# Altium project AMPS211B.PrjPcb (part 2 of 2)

## Sheet AMPS211B_PwrMod_Regs.SchDoc: AMPS211B_PwrMod_Regs
size 431 x 279 mm; Date: Not shown in title block; ApprovedBy: Not shown in title block; CheckedBy: Not shown in title block; Author: Not shown in title block; CompanyName: Not shown in title block; Engineer: Not shown in title block; Organization: Not shown in title block; Address1: Not shown in title block; Address2: Not shown in title block; Address3: Not shown in title block; Address4: Not shown in title block; DocumentNumber: 2; Revision: Use project parameter SCH_Rev; SheetNumber: 2; SheetTotal: 4; PageSetup: Record=PageOptions¦CenterHorizontal=True¦CenterVertical=True¦PrintScale=1.00¦XCorrection=1.00¦YCorrection=1.00¦PrintKind=0¦BorderSize=5000000¦LeftOffset=0¦BottomOffset=0¦Orientation=2¦PaperLength=1000¦PaperWidth=1000¦Scale=100¦PaperSource=15¦PrintQuality=600¦MediaType=1¦DitherType=10¦PaperKind=Letter¦PrintScaleMode=1
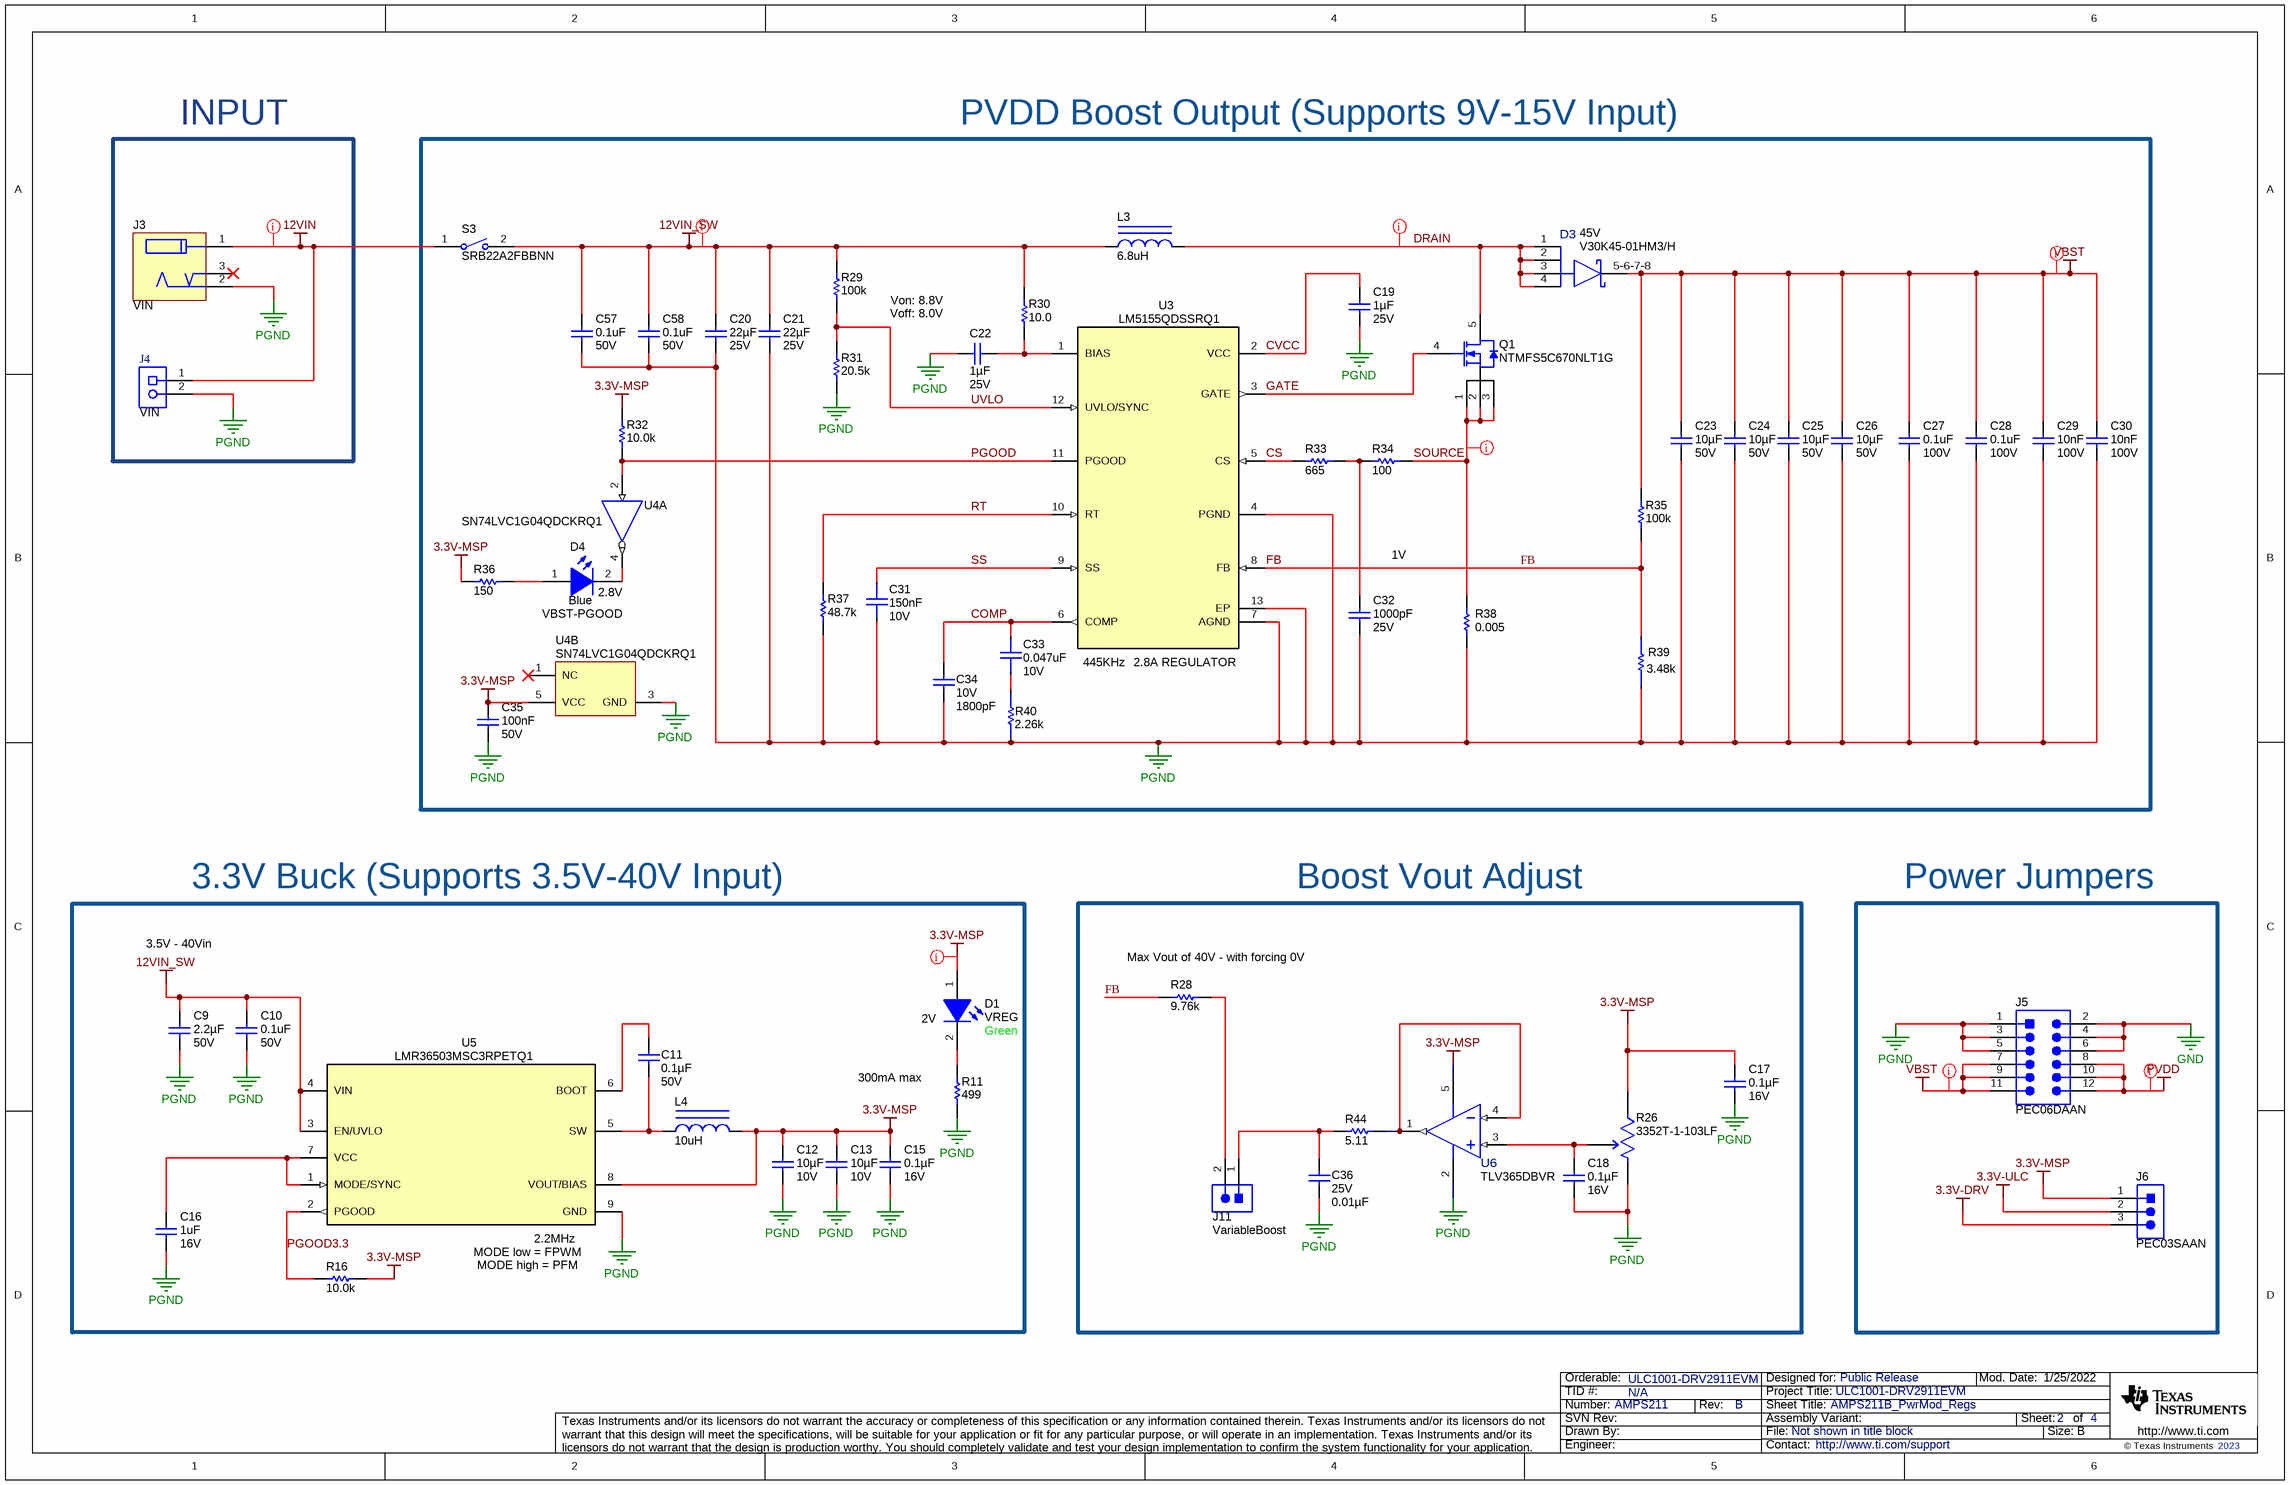
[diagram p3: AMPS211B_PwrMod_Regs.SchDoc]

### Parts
C9  Cap_F: 2.2µF  VDC_V: 50V  [0805L]  (hidden comment: CGA4J3X7R1H225K125AB)
C10  VDC_V: 50V  ValueDisplayed: 0.1uF  [0603L]  (hidden comment: CGA3E2X7R1H104K080AA)
C11  ValueDisplayed: 0.1µF  VDC_V: 50V  [0402L]  (hidden comment: CGA2B3X7R1H104K050BD)
C12  Cap_F: 10µF  VDC_V: 10V  [0805L]  (hidden comment: GCJ21BR71A106KE01L)
C13  Cap_F: 10µF  VDC_V: 10V  [0805L]  (hidden comment: GCJ21BR71A106KE01L)
C15  VDC_V: 16V  ValueDisplayed: 0.1µF  [0402L]  (hidden comment: GCM155R71C104JA55D)
C16  VDC_V: 16V  ValueDisplayed: 1uF  [0402L]  (hidden comment: EMK105BJ105KVHF)
C17  VDC_V: 16V  ValueDisplayed: 0.1µF  [0402L]  (hidden comment: GCM155R71C104JA55D)
C18  VDC_V: 16V  ValueDisplayed: 0.1µF  [0402L]  (hidden comment: GCM155R71C104JA55D)
C19  Cap_F: 1µF  VDC_V: 25V  [0603S]  (hidden comment: GCM188R71E105KA64D)
C20  VDC_V: 25V  ValueDisplayed: 22µF  [1210_270L]  (hidden comment: CL32B226KAJNFNE)
C21  VDC_V: 25V  ValueDisplayed: 22µF  [1210_270L]  (hidden comment: CL32B226KAJNFNE)
C22  Cap_F: 1µF  VDC_V: 25V  [0603S]  (hidden comment: GCM188R71E105KA64D)
C23  VDC_V: 50V  ValueDisplayed: 10µF  [1210_270L]  (hidden comment: CL32B106KBJNNWE)
C24  VDC_V: 50V  ValueDisplayed: 10µF  [1210_270L]  (hidden comment: CL32B106KBJNNWE)
C25  VDC_V: 50V  ValueDisplayed: 10µF  [1210_270L]  (hidden comment: CL32B106KBJNNWE)
C26  VDC_V: 50V  ValueDisplayed: 10µF  [1210_270L]  (hidden comment: CL32B106KBJNNWE)
C27  VDC_V: 100V  ValueDisplayed: 0.1uF  [0603S]  (hidden comment: GRM188R72A104KA35J)
C28  VDC_V: 100V  ValueDisplayed: 0.1uF  [0603S]  (hidden comment: GRM188R72A104KA35J)
C29  Cap_F: 10nF  VDC_V: 100V  [0603S]  (hidden comment: CGA3E2X7R2A103K080AA)
C30  Cap_F: 10nF  VDC_V: 100V  [0603S]  (hidden comment: CGA3E2X7R2A103K080AA)
C31  ValueDisplayed: 150nF  VDC_V: 10V  [FP-CGA2B1X7R1A154M050BC_0402-MFG]  (hidden comment: CGA2B1X7R1A154M050BC)
C32  VDC_V: 25V  ValueDisplayed: 1000pF  [0201_033L]  (hidden comment: CGA1A2X7R1E102K030BA)
C33  ValueDisplayed: 0.047uF  VDC_V: 10V  [FP-LMF105B7473KVHF_0402-MFG]  (hidden comment: LMF105B7473KVHF)
C34  VDC_V: 10V  ValueDisplayed: 1800pF  [0201L]  (hidden comment: GRM033R71A182KA01D)
C35  Cap_F: 100nF  VDC_V: 50V  [0603L]  (hidden comment: CGA3E2X7R1H104K080AA)
C36  VDC_V: 25V  ValueDisplayed: 0.01µF  [0402]  (hidden comment: CL05B103KA5NNNC)
C57  VDC_V: 50V  ValueDisplayed: 0.1uF  [0603L]  (hidden comment: CGA3E2X7R1H104K080AA)
C58  VDC_V: 50V  ValueDisplayed: 0.1uF  [0603L]  (hidden comment: CGA3E2X7R1H104K080AA)
D1  VREG  value Green  Value2: 2V  [LTST-C193_Green]
D3  V30K45-01HM3/H  Vf_V: 45V  [FP-V30K45-01HM3-H_FlatPAK5x6-MFG]
D4  VBST-PGOOD  value Blue  Value2: 2.8V  [LTST-C193_Blue]
J3  VIN  [CONN_RAPC712X]
J4  VIN  [Molex_039544-3002]
J5  PEC06DAAN  [CONN_PEC06DAAN]
J6  PEC03SAAN  [CONN_PEC03SAAN]
J11  VariableBoost  [Samtec_TSW-102-07-T-S]
L3  ValueDisplayed: 6.8uH  [XAL1010]  (hidden comment: XAL1010-682MEB)
L4  ValueDisplayed: 10uH  [XPL2010]  (hidden comment: XPL2010-103MLB)
Q1  NTMFS5C670NLT1G  [SO-8FL]
R11  ValueDisplayed: 499  [0603L]  (hidden comment: CRCW0603499RFKEAC)
R16  ValueDisplayed: 10.0k  [0402S]  (hidden comment: RC0402FR-0710KL)
R26  3352T-1-103LF  [Bourns_3352T]
R28  ValueDisplayed: 9.76k  [0402]  (hidden comment: CRCW04029K76FKED)
R29  ValueDisplayed: 100k  [0402L]  (hidden comment: ERJ-2RKF1003X)
R30  ValueDisplayed: 10.0  [0603S]  (hidden comment: CRCW060310R0FKEA)
R31  ValueDisplayed: 20.5k  [0402S]  (hidden comment: CRCW040220K5FKED)
R32  ValueDisplayed: 10.0k  [0402S]  (hidden comment: RC0402FR-0710KL)
R33  ValueDisplayed: 665  [0402S]  (hidden comment: ERJ-2RKF1000X)
R34  ValueDisplayed: 100  [0402S]  (hidden comment: ERJ-2RKF1000X)
R35  ValueDisplayed: 100k  [0603L]  (hidden comment: CRCW0603100KFKEA)
R36  ValueDisplayed: 150  [0402S]  (hidden comment: CRCW0402150RFKED)
R37  ValueDisplayed: 48.7k  [0402L]  (hidden comment: CRCW040248K7FKED)
R38  ValueDisplayed: 0.005  [CRE2512-R5_R9]  (hidden comment: CRE2512-FZ-R005E-3)
R39  value 3.48k  [FP-RK73H1JTTD3481F_0603-MFG]  (hidden comment: RK73H1JTTD3481F)
R40  Res_ohm: 2.26k  [FP-ERJ-1GNF2261C_0201-MFG]  (hidden comment: ERJ-1GNF2261C)
R44  ValueDisplayed: 5.11  [0402]  (hidden comment: CRCW04025R11FKED)
S3  SRB22A2FBBNN  [SW_SRB22A2FBBNN]
U3  LM5155QDSSRQ1  [DSS0012C]
U4  SN74LVC1G04QDCKRQ1  [DCK0005A_L]  (parts A,B of 2)
U5  LMR36503MSC3RPETQ1  [RPE0009A]
U6  TLV365DBVR  [DBV0005A-MFG]

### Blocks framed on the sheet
Max Vout of 40V - with forcing 0V: C17 C18 C36 J11 R26 R28 R44 U6

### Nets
3.3V-DRV: J6.3
3.3V-MSP: C12.1 C13.1 C15.1 C17.1 C35.1 D1.1(A) J6.1 L4.2 R16.2 R26.1(CCW) R32.1 R36.1 U4.5(VCC) U5.8(VOUT/BIAS) U6.5(V+)
3.3V-ULC: J6.2
12VIN: J3.1 J4.1 S3.1
12VIN_SW: C9.1 C10.1 C20.1 C21.1 C57.1 C58.1 L3.1 R29.2 R30.2 S3.2 U5.3(EN/UVLO) U5.4(VIN)
GND: J5.2 J5.4 J5.6
PGND: C9.2 C10.2 C12.2 C13.2 C15.2 C16.2 C17.2 C18.2 C19.2 C20.2 C21.2 C22.2 C23.2 C24.2 C25.2 C26.2 C27.2 C28.2 C29.2 C30.2 C31.2 C32.2 C34.2 C35.2 C36.2 C57.2 C58.2 J3.2 J4.2 J5.1 J5.3 J5.5 R11.1 R26.3(CW) R31.1 R37.1 R38.1 R39.1 R40.1 U3.4(PGND) U3.7(AGND) U3.13(EP) U4.3(GND) U5.9(GND) U6.2(V-)
PVDD: J5.8 J5.10 J5.12
VBST: C23.1 C24.1 C25.1 C26.1 C27.1 C28.1 C29.1 C30.1 D3.5-6-7-8(CATHODE) J5.7 J5.9 J5.11 R35.2
COMP: C33.2 C34.1 U3.6(COMP)
CS: R33.1 U3.5(CS)
CVCC: C19.1 U3.2(VCC)
DRAIN: D3.1(ANODE) D3.2(ANODE) D3.3(ANODE) D3.4(ANODE) L3.2 Q1.5(D)
FB: R28.1 R35.1 R39.2 U3.8(FB)
GATE: Q1.4(G) U3.3(GATE)
PGOOD: R32.2 U3.11(PGOOD) U4.2(A)
PGOOD3.3: R16.1 U5.2(PGOOD)
RT: R37.2 U3.10(RT)
SOURCE: Q1.1(S) Q1.2(S) Q1.3(S) R34.2 R38.2
SS: C31.1 U3.9(SS)
UVLO: R29.1 R31.2 U3.12(UVLO/SYNC)
NetC11_1: C11.1 U5.6(BOOT)
NetC11_2: C11.2 L4.1 U5.5(SW)
NetC16_1: C16.1 U5.1(MODE/SYNC) U5.7(VCC)
NetC18_1: C18.1 R26.2(WIPER) U6.3(+IN)
NetC22_1: C22.1 R30.1 U3.1(BIAS)
NetC32_1: C32.1 R33.2 R34.1
NetC33_1: C33.1 R40.2
NetC36_1: C36.1 J11.1 R44.1
NetD1_2: D1.2(K) R11.2
NetD4_1: D4.1(A) R36.2
NetD4_2: D4.2(K) U4.4(Y)
NetJ11_2: J11.2 R28.2
NetR44_2: R44.2 U6.1(VOUT) U6.4(-IN)

Not connected (* = marked no-connect by the designer): J3 3*; U4 1(NC)*

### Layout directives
net class Power: 3.3V-MSP, 12VIN, 12VIN_SW, DRAIN, PVDD, SOURCE, VBST

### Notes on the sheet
- INPUT
- PVDD Boost Output (Supports 9V-15V Input)
- Von: 8.8V
- Voff: 8.0V
- 1V
- (near U3) 445KHz
- (near U3) 2.8A REGULATOR
- 3.3V Buck (Supports 3.5V-40V Input)
- Boost Vout Adjust
- Power Jumpers
- 3.5V - 40Vin
- 300mA max
- (near U5) 2.2MHz
- (near U5) MODE low = FPWM
- (near U5) MODE high = PFM

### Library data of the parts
C9 = CMP-0007977-2: CAP, CERM, 2.2 uF, 50 V, +/- 10%, X7R, AEC-Q200 Grade 1, 0805; Manufacturer: TDK; TaMin_C: -55°C; ESR_ohm: 3.288m; Polarized: N; SizeAreaWB_mm2: 6.75; Value1: 0.003288 ohm; U/M: EA; Value: 2.2uF; TaMax_C: 125°C; SizeZ_mm: 1.45; SizeX_mm: 2; SizeY_mm: 1.25; Cap_Case: 0805; SizeArea_mm2: 2.5; AEC Qualified: Y; IRMS_A: 3.6003A; AEC Grade: 1; AEC Category: Q200
C10 C57 C58 = CMP-0007078-4: CAP, CERM, 0.1 uF, 50 V, +/- 10%, X7R, AEC-Q200 Grade 1, 0603; Manufacturer: TDK; TaMin_C: -55°C; ESR_ohm: 0.0296; Polarized: N; SizeAreaWB_mm2: 4.68; Value1: 0.0296 ohm; U/M: EA; Value: 0.1uF; TaMax_C: 125°C; SizeZ_mm: 1; SizeX_mm: 1.6; SizeY_mm: 0.8; Cap_Case: 0603; SizeArea_mm2: 1.28; AEC Qualified: Y; Cap_F: 100nF; IRMS_A: 971.99mA; AEC Category: Q200
C11 = CMP-0084548-1: CAP, CERM, 0.1 µF, 50 V,+/- 10%, X7R, AEC-Q200 Grade 1, 0402; Manufacturer: TDK; SizeZ_mm: 0.6; TaMax_C: 125°C; Cap_F: 100nF; Polarized: N; SizeX_mm: 1; Value: 0.1uF; AEC Category: Q200; TaMin_C: -55°C; SizeArea_mm2: 0.5; SizeAreaWB_mm2: 3; Cap_Case: 0402; U/M: EA; AEC Qualified: Y
C12 C13 = CMP-0079153-1: CAP, CERM, 10 µF, 10 V,+/- 10%, X7R, AEC-Q200 Grade 1, 0805; Manufacturer: MuRata; SizeAreaWB_mm2: 6.75; SizeArea_mm2: 2.5; AEC Qualified: Y; AEC Category: Q200; Value: 10uF; TaMax_C: 125°C; SizeZ_mm: 1.45; AEC Grade: 1; Polarized: N; TaMin_C: -55°C; SizeY_mm: 1.25; U/M: EA; SizeX_mm: 2; Cap_Case: 0805
C15 C17 C18 = CMP-0080702-1: CAP, CERM, 0.1 µF, 16 V,+/- 5%, X7R, AEC-Q200 Grade 1, 0402; Manufacturer: MuRata; Cap_F: 100nF; SizeAreaWB_mm2: 3; SizeArea_mm2: 0.5; AEC Qualified: Y; AEC Category: Q200; Value: 0.1uF; TaMax_C: 125°C; SizeZ_mm: 0.6; AEC Grade: 1; Polarized: N; TaMin_C: -55°C; U/M: EA; Cap_Case: 0402
C16 = CMP-0006347-2: CAP, CERM, 1 uF, 16 V, +/- 10%, X5R, 0402; Manufacturer: Taiyo Yuden; TaMin_C: -55°C; Polarized: N; SizeAreaWB_mm2: 3; Value1: Unknown; U/M: EA; Value: 1uF; TaMax_C: 85°C; SizeZ_mm: 0.6; SizeX_mm: 1; SizeY_mm: 0.5; Cap_Case: 0402; Cap_F: 1µF; AEC Category: Q200
C19 C22 = CMP-0007139-4: CAP, CERM, 1 uF, 25 V, +/- 10%, X7R, AEC-Q200 Grade 1, 0603; Manufacturer: MuRata; TaMin_C: -55°C; Polarized: N; SizeAreaWB_mm2: 4.68; Value1: Unknown; U/M: EA; Value: 1uF; TaMax_C: 125°C; SizeZ_mm: 1; SizeX_mm: 1.6; SizeY_mm: 0.8; Cap_Case: 0603; SizeArea_mm2: 1.28; AEC Qualified: Y; AEC Category: Q200
C20 C21 = CMP-0080066-1: CAP, CERM, 22 µF, 25 V,+/- 10%, X7R, 1210; Manufacturer: Samsung Electro-Mechanics; TaMin_C: -55°C; Polarized: N; SizeAreaWB_mm2: 14.7; U/M: EA; Value: 22uF; TaMax_C: 125°C; SizeZ_mm: 2.7; SizeX_mm: 3.2; SizeY_mm: 2.5; Cap_Case: 1210; SizeArea_mm2: 8; AEC Category: Q200
C23-C26 = CMP-0079201-1: CAP, CERM, 10 µF, 50 V,+/- 10%, X7R, 1210; Manufacturer: Samsung Electro-Mechanics; TaMin_C: -55°C; ESR_ohm: 5m; Polarized: N; SizeAreaWB_mm2: 14.7; Value1: 0.005 ohm; U/M: EA; Value: 10uF; TaMax_C: 125°C; SizeZ_mm: 2.7; SizeX_mm: 3.2; SizeY_mm: 2.5; Cap_Case: 1210; SizeArea_mm2: 8; AEC Category: Q200
C27 C28 = CMP-0007470-5: CAP, CERM, 0.1 uF, 100 V, +/- 10%, X7R, 0603; Manufacturer: MuRata; TaMin_C: -55°C; Polarized: N; SizeAreaWB_mm2: 4.68; Value1: Unknown; U/M: EA; Value: 0.1uF; TaMax_C: 125°C; SizeZ_mm: 1; SizeX_mm: 1.6; SizeY_mm: 0.8; Cap_Case: 0603; SizeArea_mm2: 1.28; CompType: Capacitor; Cap_F: 100nF; AEC Category: Q200
C29 C30 = CMP-0007082-4: CAP, CERM, 0.01 uF, 100 V, +/- 10%, X7R, AEC-Q200 Grade 1, 0603; Manufacturer: TDK; TaMin_C: -55°C; ESR_ohm: 2.35428d; Polarized: N; SizeAreaWB_mm2: 4.68; Value1: 0.235428 ohm; U/M: EA; Value: 0.01uF; TaMax_C: 125°C; SizeZ_mm: 1; SizeX_mm: 1.6; SizeY_mm: 0.8; Cap_Case: 0603; SizeArea_mm2: 1.28; CompType: Capacitor; AEC Qualified: Y; IRMS_A: 3.96995dA; AEC Category: Q200
C31 = CMP-0088625-1: 0.15µF ±20% 10V Ceramic Capacitor X7R 0402 (1005 Metric); Manufacturer: TDK; AEC Grade: Grade 1; AEC Qualified: Yes; TempCo: 15%; SizeZ_mm: 0.55mm
C32 = CMP-0009645-3: CAP, CERM, 1000 pF, 25 V, +/- 10%, X7R, AEC-Q200 Grade 1, 0201; Manufacturer: TDK; TaMin_C: -55°C; ESR_ohm: 2.5722; Polarized: N; SizeAreaWB_mm2: 2.08; Value1: 2.5722 ohm; U/M: EA; Value: 1000pF; TaMax_C: 125°C; SizeZ_mm: 0.33; SizeX_mm: 0.6; SizeY_mm: 0.3; Cap_Case: 0201_033; SizeArea_mm2: 0.18; AEC Qualified: Y; Cap_F: 1nF; IRMS_A: 143.158mA; AEC Grade: 1; AEC Category: Q200
C33 = CMP-0088629-1: Multilayer Ceramic Capacitor 0.047uF 10V 10% 0402 Paper T/R; Manufacturer: Taiyo Yuden; Cap_F: 47nF; AEC Qualified: Yes; Temperature Characteristic: X7R; TempCo: 15%; AEC Grade: Grade 1; SizeZ_mm: 0.55mm
C34 = CMP-0009735-1: CAP, CERM, 1800 pF, 10 V, +/- 10%, X7R, 0201; Manufacturer: MuRata; TaMin_C: -55°C; Polarized: N; SizeAreaWB_mm2: 2.08; Value1: Unknown; U/M: EA; Value: 1800pF; TaMax_C: 125°C; SizeZ_mm: 0.26; SizeX_mm: 0.6; SizeY_mm: 0.3; Cap_Case: 0201; SizeArea_mm2: 0.18; Cap_F: 1.8nF; AEC Category: Q200
C35 = CMP-0007078-4: CAP, CERM, 0.1 uF, 50 V, +/- 10%, X7R, AEC-Q200 Grade 1, 0603; Manufacturer: TDK; TaMin_C: -55°C; ESR_ohm: 0.0296; Polarized: N; SizeAreaWB_mm2: 4.68; Value1: 0.0296 ohm; U/M: EA; Value: 0.1uF; TaMax_C: 125°C; SizeZ_mm: 1; SizeX_mm: 1.6; SizeY_mm: 0.8; Cap_Case: 0603; SizeArea_mm2: 1.28; AEC Qualified: Y; IRMS_A: 971.99mA; AEC Category: Q200
C36 = CMP-0860561-1: CAP, CERM, 0.01 µF, 25 V,+/- 10%, X7R, 0402; Manufacturer: Samsung Electro-Mechanics; U/M: EA; SizeArea_mm2: 0.5; Value: 0.01uF; TaMin_C: -55°C; SizeZ_mm: 0.6; Polarized: N; SizeX_mm: 1; TaMax_C: 125°C; SizeAreaWB_mm2: 3; Cap_F: 10nF; AEC Category: Q200
D1 = CMP-0079921-3: LED, Green, SMD; PartNumber: LTST-C193KGKT-5A; Manufacturer: Lite-On; Tjmax_C: 85°C; SizeY_mm: 0.8; Io_A: 5mA; SizeAreaWB_mm2: 4.68; Type: AlInGaP; SizeX_mm: 1.6; SizeZ_mm: 0.45; SizeArea_mm2: 1.28; Value1: W
D3 = CMP-0088390-3: Diode Schottky 45V 30A Surface Mount FlatPAK (5x6); Manufacturer: Vishay; ValueDisplayed: 4000pF; AEC Category: Q101; SizeZ_mm: 1.09mm; AEC Grade: Grade 0; AEC Qualified: Yes; TJmax_C: 150°C; Forward Current: 5A; Peak Reverse Current: 2mA; Max Surge Forward Current: 240A
D4 = CMP-0002938-3: LED, Blue, SMD; PartNumber: LTST-C193TBKT-5A; Manufacturer: Lite-On; Angle: 130; Power_TotalModule: 76mW; Type: InGaN; Tjmax_C: 80°C; Value1: 0.076W; Io_A: 5mA; Ir_A: 10µA; LuminousIntensity_IV: 15
J3 = CMP-0074931-1: Power Jack, mini, 2.5mm OD, R/A, TH; Manufacturer: Switchcraft; PartNumber: RAPC712X; CNHeader: False; Green_Lifecycle: Not Set; Green_REACh: Incomplete
J4 = CMP-0055345-1: Terminal Block, 5.08mm, 2x1, TH; Manufacturer: Molex; PartNumber: 039544-3002; CNHeader: FALSE; Current_A: 15A; Gender: Female; Voltage_V: 300V; Row_Count: 1; Pitch_mm: 5.08; ContactFinish: Tin; CT: TRUE; Cert_UL: Y
J5 = CMP-0054551-2: Header, 100mil, 6x2, Tin, TH; Manufacturer: Sullins Connector Solutions; Current_A: 3A; Green_Lifecycle: Not Set; Shrouded: N; Gender: Male; Green_REACh: Incomplete; Voltage_V: 1.8kV; Row_Count: 2; RowSpacing_mm: 2.54; Cert_UL: Y
J6 = CMP-0002338-1: Header, 100mil, 3x1, Tin, TH; Manufacturer: Sullins Connector Solutions; CNHeader: TRUE; Current_A: 3A; Green_Lifecycle: Not Set; Shrouded: N; Gender: Male; Green_REACh: Incomplete; Voltage_V: 1.8kV; Row_Count: 1; Pitch_mm: 2.54; CT: FALSE; Cert_UL: Y
J11 = CMP-0075508-2: Header, 2.54 mm, 2x1, Tin, TH; PartNumber: TSW-102-07-T-S; Manufacturer: Samtec; Pitch_mm: 2.54; Cert_VDE: N; Gender: Male; Cert_CSA: Y; Voltage_V: 550V; Green_REACh: Passed; Current_A: 6.3A; Green_Lifecycle: Active; Row_Count: 1
L3 = CMP-0060953-1: Inductor, Shielded, Composite, 6.8 uH, 18.5 A, 0.01 ohm, SMD; Manufacturer: Coilcraft; Isat: 21.8A @ 30% inductance drop; Irms: 18.5A @ 40C rise; Green_Lifecycle: Not Set; SizeAreaWB_mm2: 159.6; DCR_ohm: 10m; Green_REACh: Incomplete; Value: 6.8uH; Imax_A: 18.5A; SizeZ_mm: 10; SizeX_mm: 11.3; SizeArea_mm2: 113; Ind_H: 6.8µH; AEC Category: Q200
L4 = CMP-0061167-1: Inductor, Shielded, Composite, 10 uH, 0.61 A, 0.56 ohm, SMD; Manufacturer: Coilcraft; Isat: 0.61A @ 30% inductance drop; Irms: 0.66A @ 40C rise; Green_Lifecycle: Not Set; SizeAreaWB_mm2: 8.7; DCR_ohm: 0.56; Green_REACh: Incomplete; Value: 10uH; Imax_A: 610mA; SizeZ_mm: 1; SizeX_mm: 2; SizeY_mm: 1.9; Value2: 0.61A; SizeArea_mm2: 3.8; Ind_H: 10µH; AEC Category: Q200
Q1 = CMP-0000853-1: MOSFET, N-CH, 60 V, 71 A, SO-8FL; Alternate Manufacturer: None; Manufacturer: ON Semiconductor; SizeZ_mm: 1.1; ChType: N; Value2: 20 nC; Value1: 0.008; VdsMax_V: 60V; SizeX_mm: 6.15; SizeY_mm: 5.15; Vgs_V: 20V; Value: 60V; Rdson45_ohm: 8.8m; SizeArea_mm2: 31.6725; AEC Category: Q101; IdsMax_A: 71A; SizeAreaWB_mm2: 58.2725; U/M: EA; QgTyp_nC: 20
R11 = CMP-0082532-1: RES, 499, 1%, 0.1 W, 0603; Manufacturer: Vishay-Dale; Value: 499; Value_Code: 499R; Power_W: 100mW; Value2: 0.1W; VDC_V: 75V; TempCo: 100 ppm/C; EIA_Code: E96; SizeAreaWB_mm2: 4.68; SizeX_mm: 1.6; SizeY_mm: 0.8; SizeZ_mm: 1; SizeArea_mm2: 1.28; AEC Qualified: N; AEC Category: Q200
R16 R32 = CMP-0078669-1: RES, 10.0 k, 1%, 0.063 W, 0402; Manufacturer: Yageo America; Power_W: 63mW; Green_Lifecycle: Active; TempCo: 100 ppm/C; Value_Code: 10k0; Green_REACh: Passed; Value: 10.0k; EIA_Code: E96; Res_ohm: 10k; SizeX_mm: 1; SizeY_mm: 0.5; SizeZ_mm: 0.6; Value2: 0.063W; CompType: Resistor; AEC Qualified: N; AEC Category: Q200
R26 = CMP-0093882-3: 10 kOhms 0.5W, 1/2W Through Hole Thumbwheel Potentiometer Top Adjustment; Manufacturer: Bourns; Value: 10kΩ; Voltage: 250V; TempCo: 100ppm/°C; Standoff Height: 0.64mm; Tolerance_%: 20%; Power: 500mW; AEC Qualified: No; SizeZ_mm: 4.32mm
R28 = CMP-0026622-3: RES, 9.76 k, 1%, 0.063 W, AEC-Q200 Grade 0, 0402; Manufacturer: Vishay-Dale; AEC Category: Q200; AEC Qualified: Y; AEC Grade: 0; Value2: 0.063W; Value_Code: 9k76; SizeY_mm: 0.5; SizeZ_mm: 0.6; VDC_V: 50V; SizeX_mm: 1; Value: 9.76k; Power_W: 63mW; EIA_Code: E96; TempCo: 100 ppm/C
R29 = CMP-0026659-2: RES, 100 k, 1%, 0.1 W, 0402; Manufacturer: Panasonic; Power_W: 100mW; TempCo: 100 ppm/C; U/M: EA; Value: 100k; EIA_Code: E96; SizeX_mm: 1; SizeY_mm: 0.5; SizeZ_mm: 0.6; Value2: 0.1W; AEC Qualified: Yes; VDC_V: 50V; AEC Category: Q200; AEC Grade: 0
R30 = CMP-0022003-4: RES, 10.0, 1%, 0.1 W, AEC-Q200 Grade 0, 0603; Manufacturer: Vishay-Dale; Power_W: 100mW; TempCo: 100 ppm/C; Value_Code: 10R0; Value: 10.0; EIA_Code: E96; Res_ohm: 10; SizeX_mm: 1.6; SizeY_mm: 0.8; SizeZ_mm: 1; Value2: 0.1W; SizeArea_mm2: 1.28; AEC Qualified: Y; VDC_V: 75V; AEC Category: Q200; AEC Grade: 0
R31 = CMP-0026163-2: RES, 20.5 k, 1%, 0.063 W, AEC-Q200 Grade 0, 0402; Manufacturer: Vishay-Dale; Power_W: 63mW; TempCo: 100 ppm/C; Value_Code: 20k5; Value: 20.5k; EIA_Code: E96; SizeX_mm: 1; SizeY_mm: 0.5; SizeZ_mm: 0.6; Value2: 0.063W; AEC Qualified: Y; VDC_V: 50V; AEC Category: Q200; AEC Grade: 0
R33 = CMP-0026501-2: RES, 665, 1%, 0.063 W, AEC-Q200 Grade 0, 0402; Manufacturer: Vishay-Dale; PartNumber: CRCW0402665RFKED; Power_W: 63mW; TempCo: 100 ppm/C; Value_Code: 665R; Value: 665; EIA_Code: E96; SizeX_mm: 1; SizeY_mm: 0.5; SizeZ_mm: 0.6; Value2: 0.063W; AEC Qualified: Y; VDC_V: 50V; AEC Category: Q200; AEC Grade: 0
R34 = CMP-0026656-1: RES, 100, 1%, 0.1 W, 0402; Manufacturer: Panasonic; Power_W: 100mW; TempCo: 100 ppm/C; Value_Code: 100R; U/M: EA; Value: 100; EIA_Code: E96; SizeX_mm: 1; SizeY_mm: 0.5; SizeZ_mm: 0.6; Value2: 0.1W; VDC_V: 50V; AEC Category: Q200
R35 = CMP-0021990-4: RES, 100 k, 1%, 0.1 W, AEC-Q200 Grade 0, 0603; Manufacturer: Vishay-Dale; Power_W: 100mW; TempCo: 100 ppm/C; Value: 100k; EIA_Code: E96; SizeX_mm: 1.6; SizeY_mm: 0.8; SizeZ_mm: 1; Value2: 0.1W; SizeArea_mm2: 1.28; AEC Qualified: Y; VDC_V: 75V; AEC Category: Q200; AEC Grade: 0
R36 = CMP-0026022-3: RES, 150, 1%, 0.063 W, AEC-Q200 Grade 0, 0402; Manufacturer: Vishay-Dale; Power_W: 63mW; TempCo: 100 ppm/C; Value_Code: 150R; Value: 150; EIA_Code: E96; SizeX_mm: 1; SizeY_mm: 0.5; SizeZ_mm: 0.6; Value2: 0.063W; AEC Qualified: Y; VDC_V: 50V; AEC Category: Q200; AEC Grade: 0
R37 = CMP-0026399-2: RES, 48.7 k, 1%, 0.063 W, AEC-Q200 Grade 0, 0402; Manufacturer: Vishay-Dale; Power_W: 63mW; TempCo: 100 ppm/C; Value_Code: 48k7; Value: 48.7k; EIA_Code: E96; SizeX_mm: 1; SizeY_mm: 0.5; SizeZ_mm: 0.6; Value2: 0.063W; AEC Qualified: Y; VDC_V: 50V; AEC Category: Q200; AEC Grade: 0
R38 = CMP-0015751-2: RES, 0.005, 1%, 3 W, AEC-Q200 Grade 0, 2512; Manufacturer: Bourns; Power_W: 3W; TempCo: 75 ppm/C; Value_Code: 5L000; U/M: EA; Value: 0.005; EIA_Code: E96; Res_ohm: 5m; SizeX_mm: 6.45; SizeY_mm: 3.35; SizeZ_mm: 0.9; SizeArea_mm2: 21.6075; AEC Qualified: Y; AEC Grade: 0; AEC Category: Q200
R39 = CMP-0098378-1: 3.48 kOhms ±1% 0.1W, 1/10W Chip Resistor 0603 (1608 Metric) Automotive AEC-Q200, Moisture Resistant Thick Film; Manufacturer: KOA Speer; Approved Alternate Part Number: 541-1.00HHCT-ND; AEC Grade: Grade 0; AEC Qualified: Yes; Power_W: 100mW; SizeZ_mm: 0.55mm; TempCo: 100ppm/°C; VDC_V: 75V; Standoff Height: 0mm
R40 = CMP-0088609-1: Res Thick Film 0201 2.26K Ohm 1% 1/20W ±200ppm/°C Molded SMD SMD T/R; Manufacturer: Panasonic Electronic Components; TempCo: 200%; VDC_V: 25V; SizeZ_mm: 0.26mm; AEC Grade: Grade 1; Power_W: 50mW; AEC Qualified: Yes
R44 = CMP-0026477-2: RES, 5.11, 1%, 0.063 W, AEC-Q200 Grade 0, 0402; Manufacturer: Vishay-Dale; Power_W: 63mW; TempCo: 100 ppm/C; Value_Code: 5R11; Value: 5.11; EIA_Code: E96; SizeX_mm: 1; SizeY_mm: 0.5; SizeZ_mm: 0.6; Value2: 0.063W; AEC Qualified: Y; VDC_V: 50V; AEC Category: Q200; AEC Grade: 0
S3 = CMP-0002275-1: Switch, SPST, Off-On, 10A, 125 V, TH; Manufacturer: Conergy; CurrentRating_mA: 10kA; PositionCount: 1; VDC_V: 125V
U3 = CMP-0081539-1: Automotive Grade 2.2-MHz Wide Input Non-synchronous Boost Controller, DSS0012C (WSON-12); Alternate PartNumber: LM5155QDSSTQ1; Alternate Manufacturer: Texas Instruments; SizeAreaWB_mm2: 12; SizeZ_mm: 0.8; SizeX_mm: 2; SizeY_mm: 3; SizeArea_mm2: 6; CompType: IC; AEC Qualified: Y; AEC Category: Q200
U4 = CMP-0051661-3: Automotive Catalog Single Inverter, DCK0005A, LARGE T&R; Manufacturer: Texas Instruments; Generic Part Number: SN74LVC1G04-Q1; Logic: Inverting; Input Type: CMOS/TTL; 3-State Output: No; Voltage(Nom)(V): 1.8,2.5,3.3,5; tpd @ Nom Voltage(Max)(ns): 7.5,5.2,4.2,3.7; Sub-Family: Inverting Buffer/Driver; Bits(#): 1; VCC(Min)(V): 1.65; F @ Nom Voltage(Max)(Mhz): 150; ICC @ Nom Voltage(Max)(mA): 0.01; Technology Family: LVC; Output Drive (IOL/IOH)(Max)(mA): 32/-32; Output Type: CMOS; VCC(Max)(V): 5.5; AEC Category: Q200; AEC Qualified: Y; CompType: IC; SizeAreaWB_mm2: 9.3; SizeArea_mm2: 4.2; SizeX_mm: 2.1; SizeY_mm: 2.0; SizeZ_mm: 1.1
U5 = CMP-0750083-1: LMR36503/06-Q1 Wide Input 60-V Synchronous, DC-DC Buck Converter, RPE0009A (VQFN-9); Alternate Manufacturer: Texas Instruments; Alternate PartNumber: LMR36503MSC3RPERQ1; AEC Category: Q200; SizeY_mm: 2; SizeAreaWB_mm2: 9; AEC Qualified: Y; CompType: IC; SizeZ_mm: 1; SizeArea_mm2: 4
U6 = CMP-0032028-2: CMOS Amplifier 1 Circuit Rail-to-Rail SOT-23-5; Manufacturer: Texas Instruments; SizeZ_mm: 1.45mm; AEC Qualified: No; Gain Bandwidth: 50MHz; Input Bias Current: 0.000005uA; Input Offset Voltage: 0.4mV; Max Supply Voltage: 5.5V; Min Supply Voltage: 2.2V; Nominal Supply Current: 4.6mA; Number Of Channels: 1; Output Current Per Channel: 85mA; Response Time: 0.2us; Standoff Height: 0mm; TaMax_C: +125°C; TaMin_C: -40°C; TJmax_C: +150°C; Voltage Gain: 120dB; AEC Category: Q200; CompType: IC

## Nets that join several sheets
3.3V-DRV: AMPS211B_DUT (7 pins), AMPS211B_PwrMod_Regs (J6.3)
3.3V-MSP: AMPS211B_DUT (R3.2 R12.2), AMPS211B_MSP430 (16 pins), AMPS211B_PwrMod_Regs (15 pins)
3.3V-ULC: AMPS211B_DUT (13 pins), AMPS211B_PwrMod_Regs (J6.2)
GND: AMPS211B_DUT (35 pins), AMPS211B_Hardware (TP2.1 TP3.1), AMPS211B_MSP430 (48 pins), AMPS211B_PwrMod_Regs (J5.2 J5.4 J5.6)
PGND: AMPS211B_Hardware (TP1.1), AMPS211B_PwrMod_Regs (45 pins)
PVDD: AMPS211B_DUT (9 pins), AMPS211B_PwrMod_Regs (J5.8 J5.10 J5.12)
MSP430_SDZ: AMPS211B_DUT (R22.2), AMPS211B_MSP430 (U7.19)
OUTOFF-MSP: AMPS211B_DUT (U2.21), AMPS211B_MSP430 (U7.21)
RESETZ-MSP: AMPS211B_DUT (J13.2), AMPS211B_MSP430 (U7.22)
SCL: AMPS211B_DUT (J1.9 R1.1 TP4.1 U1.4), AMPS211B_MSP430 (J7.2)
SDA: AMPS211B_DUT (J1.10 R2.1 TP5.1 U1.3), AMPS211B_MSP430 (J9.2)

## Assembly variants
001: not fitted C55 C56 FID1 FID2 FID3 FID4 FID5 FID6 R42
